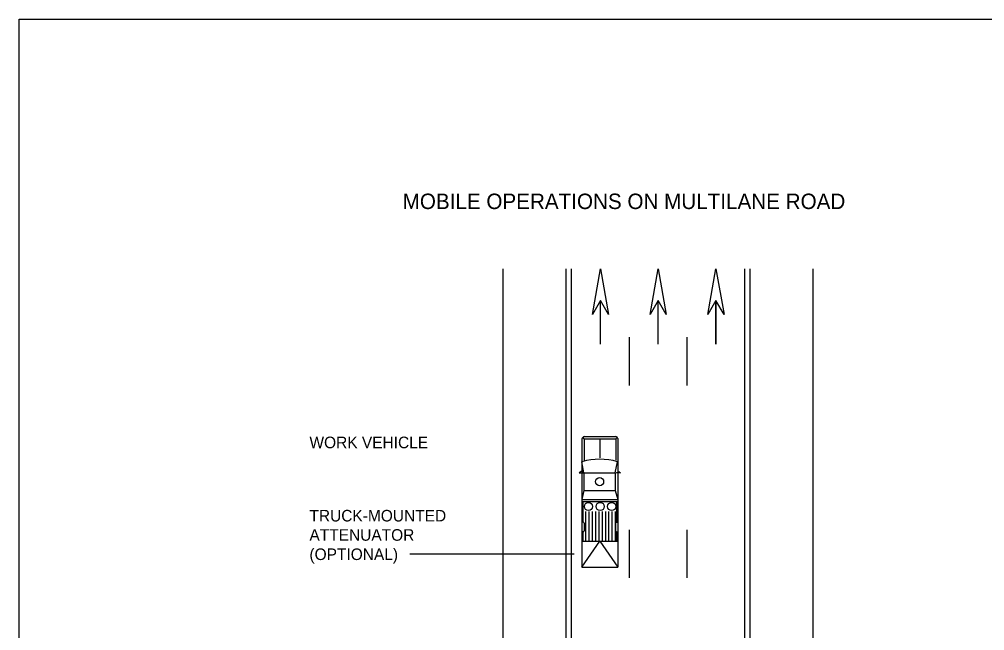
# Model space of a CAD drawing. Extents: x 49991.4 to 50021, y 49987.6 to 50011.4.
# Drawn here: x 49999.38 to 50004.39, y 49995.83 to 49999 of the extents above; entities that cross this region are included whole.
import ezdxf

# ---------------------------------------------------------------- set-up
doc = ezdxf.new("R2010")
doc.units = 0
for name, color, linetype in [('Level 1', 7, 'Continuous'), ('Level 2', 7, 'Continuous'), ('Level 3', 7, 'Continuous')]:
    doc.layers.add(name, color=color, linetype=linetype)

msp = doc.modelspace()

# ---------------------------------------------------------------- linework, layer by layer
at = {"layer": 'Level 1'}
for p, q in [((50001.8915, 49992.7699), (50001.8915, 49997.7045)), ((50002.2188, 49992.7699), (50002.2188, 49997.7045)), ((50002.2461, 49992.7699), (50002.2461, 49997.7045)), ((50003.1448, 49992.7699), (50003.1448, 49997.7045)), ((50003.172, 49992.7699), (50003.172, 49997.7045)), ((50003.4993, 49992.7699), (50003.4993, 49997.7045)), ((50002.3961, 49997.3144), (50002.3961, 49997.5403)), ((50002.3965, 49997.3144), (50002.3965, 49997.5403)), ((50002.6954, 49997.3144), (50002.6954, 49997.5403)), ((50002.6958, 49997.3144), (50002.6958, 49997.5403)), ((50002.9948, 49997.3144), (50002.9948, 49997.5403)), ((50002.9952, 49997.3144), (50002.9952, 49997.5403)), ((50002.5461, 49997.1), (50002.5461, 49997.35)), ((50002.8448, 49997.1), (50002.8448, 49997.35)), ((50002.3118, 49996.8228), (50002.3044, 49996.8318)), ((50002.3118, 49996.8349), (50002.475, 49996.8349)), ((50002.475, 49996.8228), (50002.4827, 49996.8312)), ((50002.3002, 49996.8232), (50002.3002, 49996.1579)), ((50002.3118, 49996.8228), (50002.475, 49996.8228)), ((50002.3118, 49996.8228), (50002.3118, 49996.7134)), ((50002.3934, 49996.8228), (50002.3934, 49996.7256)), ((50002.475, 49996.8228), (50002.475, 49996.7134)), ((50002.4854, 49996.8249), (50002.4854, 49996.1579)), ((50002.3104, 49996.648), (50002.3001, 49996.705)), ((50002.4721, 49996.648), (50002.485, 49996.705)), ((50002.3104, 49996.648), (50002.4721, 49996.648)), ((50002.3104, 49996.6478), (50002.3104, 49996.5557)), ((50002.4721, 49996.6478), (50002.4721, 49996.5557)), ((50002.3104, 49996.5554), (50002.3002, 49996.5091)), ((50002.3104, 49996.5554), (50002.4721, 49996.5554)), ((50002.4721, 49996.5554), (50002.4854, 49996.5091)), ((50002.3002, 49996.5091), (50002.4854, 49996.5091)), ((50002.3002, 49996.4982), (50002.4854, 49996.4982)), ((50002.3054, 49996.4982), (50002.3054, 49996.3912)), ((50002.4791, 49996.4982), (50002.4791, 49996.3912)), ((50002.3193, 49996.4475), (50002.3193, 49996.292)), ((50002.3363, 49996.4475), (50002.3363, 49996.292)), ((50002.3533, 49996.4475), (50002.3533, 49996.292)), ((50002.3704, 49996.4475), (50002.3704, 49996.292)), ((50002.3874, 49996.4475), (50002.3874, 49996.292)), ((50002.4044, 49996.4475), (50002.4044, 49996.292)), ((50002.4214, 49996.4475), (50002.4214, 49996.292)), ((50002.4384, 49996.4475), (50002.4384, 49996.292)), ((50002.4554, 49996.4475), (50002.4554, 49996.292)), ((50002.4724, 49996.4475), (50002.4724, 49996.292)), ((50002.3066, 49996.3912), (50002.3002, 49996.3912)), ((50002.3108, 49996.3869), (50002.3108, 49996.3464)), ((50002.4748, 49996.3869), (50002.4748, 49996.3464)), ((50002.479, 49996.3912), (50002.4854, 49996.3912)), ((50002.3066, 49996.3421), (50002.3002, 49996.3421)), ((50002.3054, 49996.3421), (50002.3054, 49996.292)), ((50002.479, 49996.3421), (50002.4854, 49996.3421)), ((50002.4791, 49996.3421), (50002.4791, 49996.292)), ((50002.5461, 49996.102), (50002.5461, 49996.352)), ((50002.8448, 49996.102), (50002.8448, 49996.352)), ((50002.3002, 49996.292), (50002.4854, 49996.2921)), ((50002.3002, 49996.1579), (50002.4854, 49996.1579))]:
    msp.add_line(p, q, dxfattribs=at)
for points in [[(49999.3835, 49998.9992), (50016.7501, 49998.9992), (50016.7501, 49987.7988), (49999.3835, 49987.7988)], [(50002.3545, 49997.468), (50002.3961, 49997.7045), (50002.4381, 49997.468), (50002.3961, 49997.5402)], [(50002.6538, 49997.468), (50002.6954, 49997.7045), (50002.7374, 49997.468), (50002.6954, 49997.5402)], [(50002.9532, 49997.468), (50002.9948, 49997.7045), (50003.0368, 49997.468), (50002.9948, 49997.5402)]]:
    msp.add_lwpolyline(points, close=True, dxfattribs=at)
for points in [[(50002.3073, 49996.6472), (50002.2956, 49996.6544), (50002.2859, 49996.6472), (50002.3073, 49996.6472)], [(50002.4789, 49996.6474), (50002.4906, 49996.6546), (50002.5003, 49996.6474), (50002.4789, 49996.6474)], [(50002.3002, 49996.1579), (50002.3928, 49996.292), (50002.4854, 49996.1579)]]:
    msp.add_lwpolyline(points, dxfattribs=at)
for centre in [(50002.3915, 49996.6016), (50002.3337, 49996.4728), (50002.3947, 49996.4728), (50002.454, 49996.4728)]:
    msp.add_circle(centre, 0.0211, dxfattribs=at)
for centre, radius, start, end in [((50002.3127, 49996.8224), 0.0125, 92.7859, 176.3711), ((50002.4745, 49996.8239), 0.011, 5.1286, 87.8426), ((50002.3926, 49996.3695), 0.3481, 74.595, 105.405), ((50002.3066, 49996.3869), 0.00425, 0, 90), ((50002.479, 49996.3869), 0.00425, 90, 180), ((50002.3066, 49996.3464), 0.00425, 270, 0), ((50002.479, 49996.3464), 0.00425, 180, 270)]:
    msp.add_arc(centre, radius, start, end, dxfattribs=at)
at = {"layer": 'Level 3'}
msp.add_line((50002.2602, 49996.225), (50001.4072, 49996.225), dxfattribs=at)

# ---------------------------------------------------------------- texts
at = {"layer": 'Level 2'}
for s, height, p in [('MOBILE OPERATIONS ON MULTILANE ROAD', 0.08, (50001.3707, 49998.0152)), ('WORK VEHICLE', 0.06, (50000.8875, 49996.7749)), ('TRUCK-MOUNTED', 0.06, (50000.8875, 49996.395)), ('ATTENUATOR', 0.06, (50000.8875, 49996.295)), ('(OPTIONAL)', 0.06, (50000.8875, 49996.195))]:
    msp.add_text(s, height=height, dxfattribs=at).set_placement(p)

doc.saveas('drawing.dxf')
